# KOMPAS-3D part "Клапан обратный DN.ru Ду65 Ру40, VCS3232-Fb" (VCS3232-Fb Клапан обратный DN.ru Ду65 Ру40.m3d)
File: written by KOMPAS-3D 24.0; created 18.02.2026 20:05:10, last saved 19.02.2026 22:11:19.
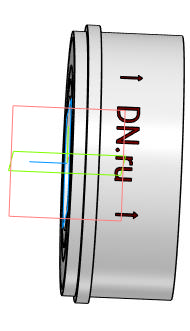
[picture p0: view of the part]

Document properties: Автор: R2D2; Полное имя файла: D:\Работа\Клапаны обратные\VCS3232-Fb Клапан обратный DN.ru Ду15-100\DN65\VCS3232-Fb Клапан обратный DN.ru Ду65 Ру40.m3d

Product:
- Body: Тело 1  | qty 1
    Масса: 1.439922
- Body: Тело 2  | qty 1
    Масса: 0.57553
- Part/product: Клапан обратный DN.ru Ду65 Ру40  | designation VCS3232-Fb
    Масса: 1.61
    Раздел спецификации: Прочие изделия
    Примечание: D100-03711
    additional columns: 1; D100-03711

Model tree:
1. Операция без истории:1
2. Операция без истории:2

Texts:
  Точка начала. Х
  Точка начала. Y
  Точка начала. Z
  VCS3232-Fb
